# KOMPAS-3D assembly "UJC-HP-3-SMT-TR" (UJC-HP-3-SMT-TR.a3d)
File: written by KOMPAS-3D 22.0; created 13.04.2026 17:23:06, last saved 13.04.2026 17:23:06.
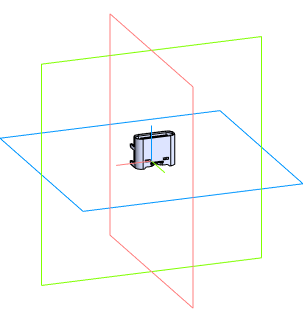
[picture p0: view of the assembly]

Document properties: Автор: Andrey; Полное имя файла: C:\Users\User1\Documents\UJC-HP-3-SMT-TR.a3d

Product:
- Component [detail]: UJC-HP-3-SMT-TR  | qty 1  | source file: UJC-HP-3-SMT-TR.m3d
- Part/product: UJC-HP-3-SMT-TR

Referenced files in C:\Users\User1\Documents\: UJC-HP-3-SMT-TR.m3d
